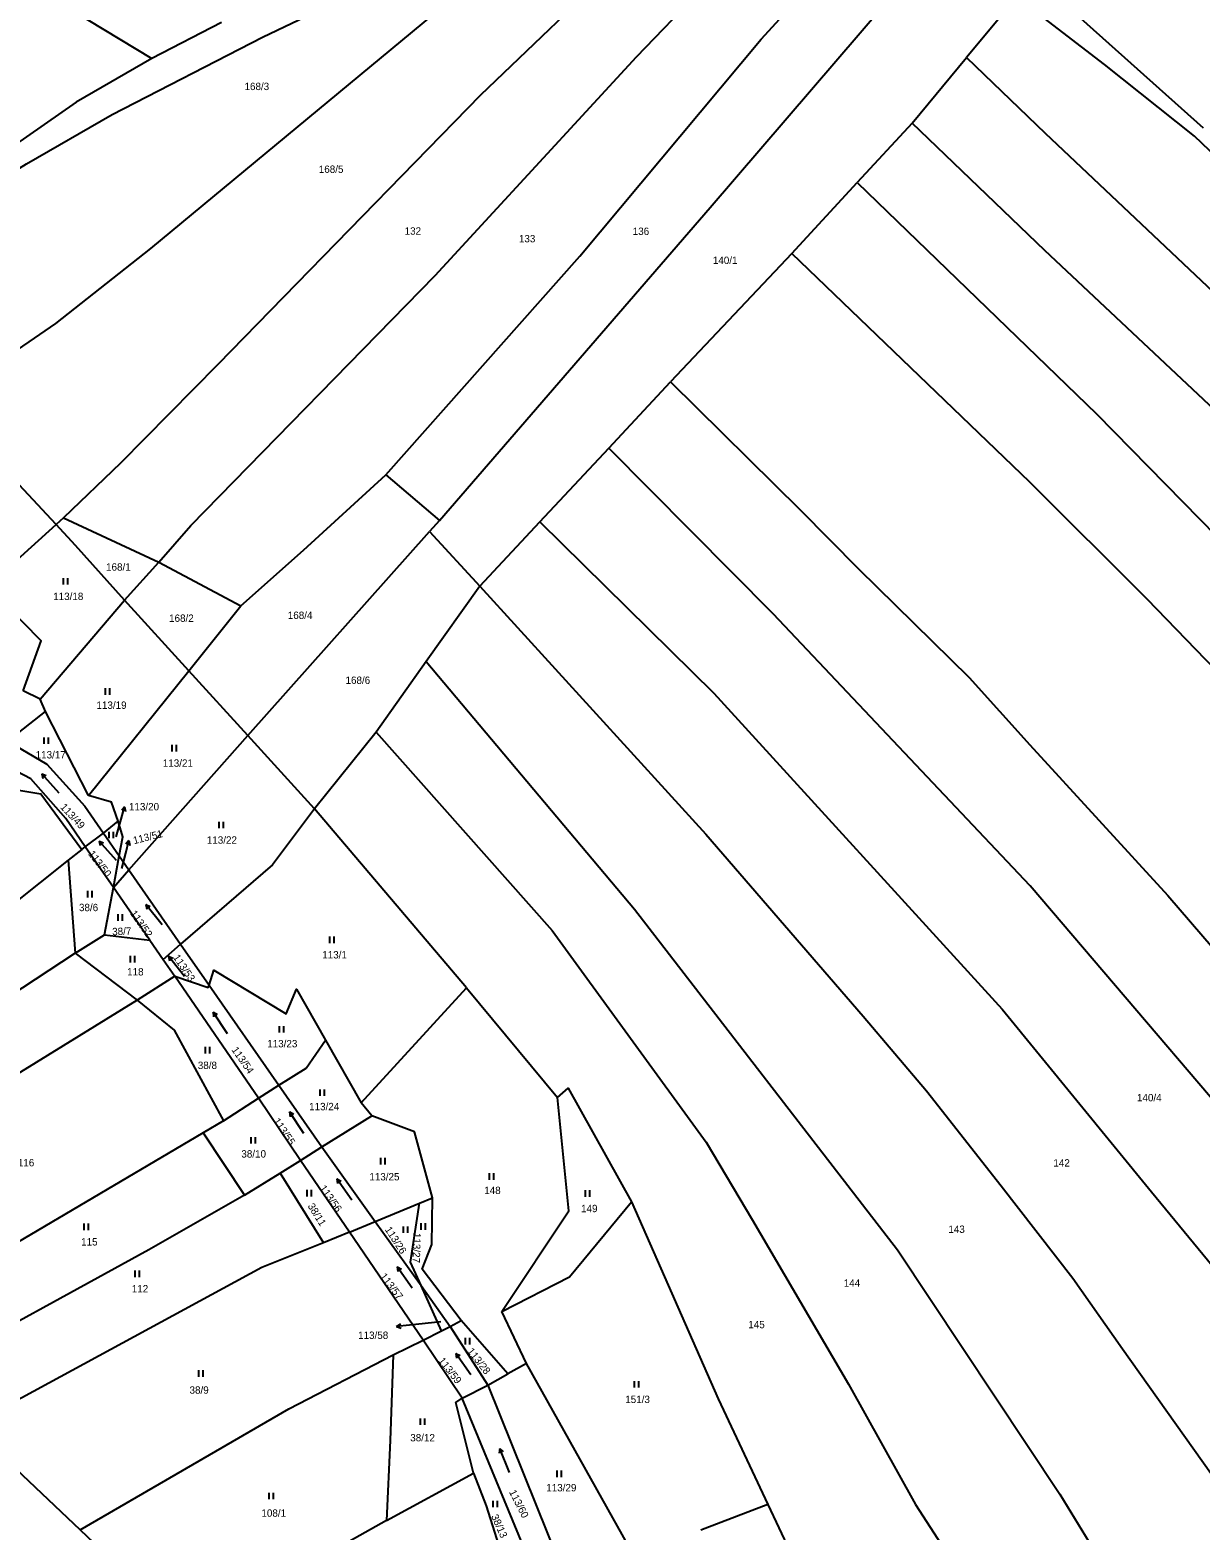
# Model space of a CAD drawing. Extents: x -751333 to -746055, y -1133395 to -1129777.
# Drawn here: x -747546.5 to -747276.5, y -1131141.4 to -1130795.4 of the extents above; entities that cross this region are included whole.
import ezdxf

# ---------------------------------------------------------------- set-up
doc = ezdxf.new("R2010")
doc.units = 0
for name, color, linetype in [('Hranice parcel', 7, 'Continuous'), ('Parcelní čísla', 7, 'Continuous'), ('Pop  PČ popisy', 7, 'Continuous'), ('Značky kultur', 7, 'Continuous')]:
    doc.layers.add(name, color=color, linetype=linetype)

msp = doc.modelspace()

# ---------------------------------------------------------------- linework, layer by layer
at = {"layer": 'Hranice parcel'}
for p, q in [((-747318.79, -1130787.77), (-747330.4, -1130801.79)), ((-747275.7, -1130818.09), (-747307.66, -1130789.55)), ((-747502.34, -1130793.69), (-747518.4, -1130801.96)), ((-747342.93, -1130816.92), (-747330.4, -1130801.79)), ((-747342.93, -1130816.92), (-747355.62, -1130830.63)), ((-747370.72, -1130846.96), (-747355.62, -1130830.63)), ((-747370.72, -1130846.96), (-747398.68, -1130876.61)), ((-747412.97, -1130891.88), (-747398.68, -1130876.61)), ((-747540.5, -1130909.52), (-747566.95, -1130881.22)), ((-747428.85, -1130908.85), (-747412.97, -1130891.88)), ((-747464.43, -1130898), (-747452.04, -1130908.53)), ((-747538.78, -1130907.97), (-747540.5, -1130909.52)), ((-747538.78, -1130907.97), (-747516.82, -1130918.2)), ((-747556.37, -1130923.79), (-747540.5, -1130909.52)), ((-747496.26, -1130958.17), (-747454.36, -1130911.13)), ((-747452.04, -1130908.53), (-747454.36, -1130911.13)), ((-747454.36, -1130911.13), (-747442.73, -1130923.69)), ((-747442.73, -1130923.69), (-747428.85, -1130908.85)), ((-747524.7, -1130926.96), (-747516.82, -1130918.2)), ((-747516.82, -1130918.2), (-747497.88, -1130928.23)), ((-747442.73, -1130923.69), (-747455.08, -1130941.09)), ((-747544.17, -1130949.82), (-747524.7, -1130926.96)), ((-747509.89, -1130943.21), (-747524.7, -1130926.96)), ((-747509.89, -1130943.21), (-747497.88, -1130928.23)), ((-747455.08, -1130941.09), (-747466.65, -1130957.41)), ((-747533.01, -1130972.03), (-747509.89, -1130943.21)), ((-747496.26, -1130958.17), (-747509.89, -1130943.21)), ((-747544.17, -1130949.82), (-747548.12, -1130947.84)), ((-747542.97, -1130952.61), (-747544.17, -1130949.82)), ((-747551.66, -1130959.44), (-747542.97, -1130952.61)), ((-747533.01, -1130972.03), (-747542.97, -1130952.61)), ((-747523.68, -1130989.16), (-747496.26, -1130958.17)), ((-747480.85, -1130975.08), (-747496.26, -1130958.17)), ((-747466.65, -1130957.41), (-747480.85, -1130975.08)), ((-747445.77, -1131016.39), (-747480.85, -1130975.08)), ((-747533.76, -1130983.87), (-747529.57, -1130980.67)), ((-747529.57, -1130980.67), (-747526.17, -1130977.92)), ((-747529.57, -1130980.67), (-747525.94, -1130985.9)), ((-747534.58, -1130984.5), (-747537.72, -1130986.92)), ((-747534.58, -1130984.5), (-747533.76, -1130983.87)), ((-747527.29, -1130993.25), (-747533.76, -1130983.87)), ((-747537.72, -1130986.92), (-747536.11, -1131008.38)), ((-747527.29, -1130993.25), (-747525.94, -1130985.9)), ((-747525.94, -1130985.9), (-747523.68, -1130989.16)), ((-747527.29, -1130993.25), (-747523.68, -1130989.16)), ((-747523.68, -1130989.16), (-747511.77, -1131006.31)), ((-747529.3, -1131004.16), (-747527.29, -1130993.25)), ((-747518.9, -1131005.41), (-747527.29, -1130993.25)), ((-747536.11, -1131008.38), (-747529.3, -1131004.16)), ((-747529.3, -1131004.16), (-747518.9, -1131005.41)), ((-747536.11, -1131008.38), (-747521.83, -1131019.25)), ((-747518.9, -1131005.41), (-747515.79, -1131009.83)), ((-747515.79, -1131009.83), (-747511.77, -1131006.31)), ((-747511.77, -1131006.31), (-747505.21, -1131015.73)), ((-747515.79, -1131009.83), (-747513.08, -1131013.69)), ((-747513.08, -1131013.69), (-747521.83, -1131019.25)), ((-747493.76, -1131041.86), (-747513.08, -1131013.69)), ((-747505.21, -1131015.73), (-747489.11, -1131038.86)), ((-747470.12, -1131042.87), (-747445.77, -1131016.39)), ((-747445.77, -1131016.39), (-747424.82, -1131041.7)), ((-747478.31, -1131028.41), (-747470.12, -1131042.87)), ((-747493.76, -1131041.86), (-747489.11, -1131038.86)), ((-747489.11, -1131038.86), (-747479.21, -1131053.09)), ((-747501.87, -1131047.09), (-747493.76, -1131041.86)), ((-747484.08, -1131056.18), (-747493.76, -1131041.86)), ((-747467.67, -1131045.88), (-747470.12, -1131042.87)), ((-747479.21, -1131053.09), (-747467.67, -1131045.88)), ((-747501.87, -1131047.09), (-747506.57, -1131049.83)), ((-747506.57, -1131049.83), (-747497.04, -1131064.23)), ((-747484.08, -1131056.18), (-747479.21, -1131053.09)), ((-747479.21, -1131053.09), (-747466.89, -1131070.28)), ((-747488.78, -1131059.1), (-747484.08, -1131056.18)), ((-747472.77, -1131072.73), (-747484.08, -1131056.18)), ((-747497.04, -1131064.23), (-747488.78, -1131059.1)), ((-747488.78, -1131059.1), (-747478.83, -1131075.18)), ((-747466.89, -1131070.28), (-747456.65, -1131066.03)), ((-747456.65, -1131066.03), (-747453.62, -1131064.84)), ((-747472.77, -1131072.73), (-747466.89, -1131070.28)), ((-747466.89, -1131070.28), (-747456.29, -1131085.07)), ((-747472.77, -1131072.73), (-747478.83, -1131075.18)), ((-747455.83, -1131097.63), (-747472.77, -1131072.73)), ((-747456.29, -1131085.07), (-747449.55, -1131094.47)), ((-747451.56, -1131095.48), (-747456.29, -1131085.07)), ((-747431.95, -1131103.02), (-747437.65, -1131091.07)), ((-747451.56, -1131095.48), (-747449.55, -1131094.47)), ((-747449.55, -1131094.47), (-747447.06, -1131093.1)), ((-747449.55, -1131094.47), (-747440.84, -1131108.03)), ((-747436.27, -1131105.41), (-747447.06, -1131093.1)), ((-747462.74, -1131101.03), (-747455.83, -1131097.63)), ((-747455.83, -1131097.63), (-747451.56, -1131095.48)), ((-747446.81, -1131111.05), (-747455.83, -1131097.63)), ((-747440.84, -1131108.03), (-747436.27, -1131105.41)), ((-747431.95, -1131103.02), (-747436.27, -1131105.41)), ((-747408.38, -1131145.07), (-747431.95, -1131103.02)), ((-747446.81, -1131111.05), (-747440.84, -1131108.03)), ((-747440.84, -1131108.03), (-747424.22, -1131149.41)), ((-747430.18, -1131151.04), (-747446.81, -1131111.05)), ((-747551.23, -1131125.94), (-747534.94, -1131141.41)), ((-747464.26, -1131139.24), (-747444.14, -1131128.36)), ((-747376.22, -1131135.6), (-747391.74, -1131141.48)), ((-747518.15, -1131157.34), (-747534.94, -1131141.41))]:
    msp.add_line(p, q, dxfattribs=at)
for points in [[(-747650.43, -1130722.5), (-747624.13, -1130740.43), (-747611.24, -1130748.86), (-747568.75, -1130772.25), (-747551.99, -1130781.63), (-747518.4, -1130801.96)], [(-747592.89, -1130855.02), (-747567.07, -1130838.41), (-747547.35, -1130826.32), (-747527.53, -1130814.88), (-747492.89, -1130797.06), (-747472.69, -1130787.42), (-747441.69, -1130763.28), (-747417.46, -1130747.1), (-747393.87, -1130731.74)], [(-747566.95, -1130881.22), (-747540.53, -1130863.15), (-747518.65, -1130845.8), (-747451.1, -1130789.94), (-747421.34, -1130761.04), (-747390.31, -1130735.18)], [(-747375.64, -1130746.37), (-747442.58, -1130810.47), (-747503.21, -1130872.55), (-747525.65, -1130895.32), (-747538.78, -1130907.97)], [(-747516.82, -1130918.2), (-747509.43, -1130909.76), (-747453.02, -1130852.06), (-747406.54, -1130801.59), (-747362.47, -1130755.89)], [(-747464.43, -1130898), (-747419.65, -1130847.56), (-747377.79, -1130797.57), (-747349.46, -1130766.63)], [(-747452.04, -1130908.53), (-747389.53, -1130836.33), (-747337.16, -1130775.31)], [(-747003.4, -1131127.9), (-747038.28, -1131074.83), (-747088.46, -1131014.6), (-747116.47, -1130986.19), (-747124.97, -1130976.78), (-747183.56, -1130913.69), (-747214.38, -1130881.51), (-747246.16, -1130850.11), (-747277.78, -1130819.92), (-747298.57, -1130803.35), (-747318.79, -1130787.77)], [(-747518.4, -1130801.96), (-747535.86, -1130812.1), (-747550.62, -1130822.39), (-747567.45, -1130834.27)], [(-747330.4, -1130801.79), (-747312.28, -1130819.2), (-747236.13, -1130891.14), (-747221.8, -1130905.72), (-747180.22, -1130949.79), (-747146.85, -1130983.32), (-747109.33, -1131021.53), (-747071.58, -1131064.23), (-747049.91, -1131090.84), (-747024.34, -1131132)], [(-747047.94, -1131136.47), (-747061.48, -1131111.93), (-747077.88, -1131090.42), (-747092.86, -1131072.81), (-747117.23, -1131044.76), (-747147.18, -1131012.65), (-747177.53, -1130980.93), (-747224.92, -1130930.97), (-747274.38, -1130881.89), (-747312.29, -1130846.28), (-747342.93, -1130816.92)], [(-747355.62, -1130830.63), (-747300.42, -1130884), (-747284.49, -1130900.18), (-747229.45, -1130956.25), (-747195.44, -1130993.87), (-747158.72, -1131032.34), (-747137.46, -1131054.25), (-747087.92, -1131108.9), (-747067.99, -1131140.68)], [(-747092.53, -1131145.47), (-747103.44, -1131128.5), (-747151.55, -1131074.46), (-747210.89, -1131009.26), (-747228.17, -1130990.46), (-747257.09, -1130959.39), (-747288.71, -1130926.72), (-747315.79, -1130899.71), (-747370.72, -1130846.96)], [(-747398.68, -1130876.61), (-747368.77, -1130906.07), (-747355.31, -1130919.74), (-747329.82, -1130944.76), (-747315.8, -1130960.3), (-747283.94, -1130995.04), (-747236.86, -1131049.77), (-747149.88, -1131157.26)], [(-747177.21, -1131162.4), (-747204.46, -1131125.99), (-747254.48, -1131065.07), (-747271.84, -1131044.18), (-747315.73, -1130992.85), (-747375, -1130930.12), (-747412.97, -1130891.88)], [(-747497.88, -1130928.23), (-747483.39, -1130915.42), (-747464.43, -1130898)], [(-747524.7, -1130926.96), (-747536.03, -1130914.31), (-747540.5, -1130909.52)], [(-747428.85, -1130908.85), (-747388.68, -1130948.41), (-747322.17, -1131021.26), (-747287.68, -1131063.4), (-747257.57, -1131100.06), (-747233.11, -1131129.78), (-747216.94, -1131150.33), (-747204.99, -1131167.77)], [(-747548.12, -1130947.84), (-747543.96, -1130936.32), (-747556.37, -1130923.79)], [(-747442.73, -1130923.69), (-747390.58, -1130980.92), (-747354.26, -1131022.92), (-747339.61, -1131040.16), (-747322.4, -1131062.04), (-747305.83, -1131083.32), (-747294.44, -1131099.65), (-747274.04, -1131128.34), (-747243.06, -1131175.98)], [(-747455.08, -1130941.09), (-747407, -1130998.24), (-747346.3, -1131076.82), (-747308.86, -1131133.19), (-747276.68, -1131185.78)], [(-747551.66, -1130959.44), (-747542.61, -1130964.81), (-747533.86, -1130974.48), (-747529.57, -1130980.67)], [(-747466.65, -1130957.41), (-747426.05, -1131003.14), (-747390.52, -1131051.98), (-747379.77, -1131069.99), (-747357.62, -1131107.84), (-747342.16, -1131135.57), (-747326.23, -1131160.19), (-747318.42, -1131169.83), (-747304.55, -1131193.5)], [(-747533.76, -1130983.87), (-747538.28, -1130977.32), (-747546.35, -1130968.19), (-747556.12, -1130963.07)], [(-747562.63, -1130968.51), (-747544.05, -1130971.62), (-747534.58, -1130984.5)], [(-747526.17, -1130977.92), (-747527.69, -1130973.54), (-747533.01, -1130972.03)], [(-747480.85, -1130975.08), (-747490.53, -1130988), (-747511.77, -1131006.31)], [(-747525.94, -1130985.9), (-747525.13, -1130981.52), (-747526.17, -1130977.92)], [(-747537.72, -1130986.92), (-747564.39, -1131008.14), (-747611.03, -1131036.67), (-747627.11, -1131046.39)], [(-747536.11, -1131008.38), (-747587.97, -1131042.46), (-747616.38, -1131059.15)], [(-747513.08, -1131013.69), (-747505.41, -1131016.33), (-747505.21, -1131015.73)], [(-747505.21, -1131015.73), (-747504.08, -1131012.3), (-747487.41, -1131022.36), (-747485.06, -1131016.72), (-747478.31, -1131028.41)], [(-747521.83, -1131019.25), (-747565.86, -1131046.34), (-747605.42, -1131071.52)], [(-747521.83, -1131019.25), (-747513.23, -1131026.12), (-747501.87, -1131047.09)], [(-747489.11, -1131038.86), (-747482.82, -1131034.88), (-747478.31, -1131028.41)], [(-747424.82, -1131041.7), (-747422.32, -1131039.54), (-747407.71, -1131065.71)], [(-747437.65, -1131091.07), (-747422.19, -1131067.82), (-747424.82, -1131041.7)], [(-747453.62, -1131064.84), (-747457.76, -1131049.58), (-747467.67, -1131045.88)], [(-747506.57, -1131049.83), (-747567.11, -1131085.51), (-747578.6, -1131091.89), (-747583.1, -1131094.79)], [(-747497.04, -1131064.23), (-747519.1, -1131076.81), (-747571.91, -1131105.73)], [(-747456.29, -1131085.07), (-747458.74, -1131079.69), (-747456.65, -1131066.03)], [(-747447.06, -1131093.1), (-747456, -1131081.28), (-747453.76, -1131075.58), (-747453.62, -1131064.84)], [(-747437.65, -1131091.07), (-747422, -1131083.03), (-747407.71, -1131065.71)], [(-747407.71, -1131065.71), (-747387.68, -1131111.18), (-747376.22, -1131135.6)], [(-747478.83, -1131075.18), (-747493.05, -1131080.92), (-747560.11, -1131117.26)], [(-747534.94, -1131141.41), (-747486.76, -1131113.5), (-747462.74, -1131101.03)], [(-747462.74, -1131101.03), (-747463.44, -1131120.77), (-747464.26, -1131139.24)], [(-747444.14, -1131128.36), (-747448.25, -1131112.03), (-747446.81, -1131111.05)], [(-747444.14, -1131128.36), (-747441.29, -1131135.89), (-747437.88, -1131146.58), (-747434.26, -1131152.16)], [(-747376.22, -1131135.6), (-747368.67, -1131151.69), (-747335.3, -1131202.07)], [(-747464.26, -1131139.24), (-747483.41, -1131150.03), (-747508, -1131163.09)]]:
    msp.add_lwpolyline(points, dxfattribs=at)
at = {"layer": 'Pop  PČ popisy'}
for p, q in [((-747526.65, -1130981.51), (-747525.51, -1130977.47)), ((-747525.51, -1130977.47), (-747524.683, -1130974.585)), ((-747524.683, -1130974.585), (-747525.44, -1130975.41)), ((-747524.683, -1130974.585), (-747524.478, -1130975.686)), ((-747523.704, -1130982.418), (-747524.432, -1130983.269)), ((-747524.43, -1130985.33), (-747523.704, -1130982.418)), ((-747523.704, -1130982.418), (-747523.46, -1130983.511)), ((-747525.3, -1130988.86), (-747524.43, -1130985.33)), ((-747461.915, -1131094.514), (-747460.971, -1131093.911)), ((-747458.93, -1131094.2), (-747461.915, -1131094.514)), ((-747461.915, -1131094.514), (-747460.866, -1131094.907)), ((-747451.68, -1131093.42), (-747458.93, -1131094.2))]:
    msp.add_line(p, q, dxfattribs=at)
at = {"layer": 'Značky kultur'}
for p, q in [((-747538.761, -1130923.37), (-747538.761, -1130921.87)), ((-747537.76, -1130923.37), (-747537.76, -1130921.87)), ((-747529.101, -1130948.78), (-747529.101, -1130947.28)), ((-747528.1, -1130948.78), (-747528.1, -1130947.28)), ((-747543.241, -1130960.1), (-747543.241, -1130958.6)), ((-747542.24, -1130960.1), (-747542.24, -1130958.6)), ((-747513.741, -1130961.83), (-747513.741, -1130960.33)), ((-747512.74, -1130961.83), (-747512.74, -1130960.33)), ((-747539.798, -1130971.471), (-747543.812, -1130967.012)), ((-747543.812, -1130967.012), (-747543.531, -1130968.074)), ((-747543.812, -1130967.012), (-747542.786, -1130967.403)), ((-747528.221, -1130981.85), (-747528.221, -1130980.35)), ((-747527.22, -1130981.85), (-747527.22, -1130980.35)), ((-747502.901, -1130979.58), (-747502.901, -1130978.08)), ((-747501.9, -1130979.58), (-747501.9, -1130978.08)), ((-747526.568, -1130986.971), (-747530.582, -1130982.512)), ((-747530.582, -1130982.512), (-747530.301, -1130983.574)), ((-747530.582, -1130982.512), (-747529.556, -1130982.903)), ((-747533.171, -1130995.51), (-747533.171, -1130994.01)), ((-747532.17, -1130995.51), (-747532.17, -1130994.01)), ((-747515.996, -1131001.813), (-747519.772, -1130997.15)), ((-747519.772, -1130997.15), (-747519.547, -1130998.225)), ((-747519.772, -1130997.15), (-747518.767, -1130997.594)), ((-747526.201, -1131000.89), (-747526.201, -1130999.39)), ((-747525.2, -1131000.89), (-747525.2, -1130999.39)), ((-747477.301, -1131006.05), (-747477.301, -1131004.55)), ((-747476.3, -1131006.05), (-747476.3, -1131004.55)), ((-747523.331, -1131010.52), (-747523.331, -1131009.02)), ((-747522.33, -1131010.52), (-747522.33, -1131009.02)), ((-747510.867, -1131013.795), (-747514.561, -1131009.067)), ((-747514.561, -1131009.067), (-747514.354, -1131010.146)), ((-747514.561, -1131009.067), (-747513.564, -1131009.528)), ((-747500.925, -1131026.978), (-747504.28, -1131022.004)), ((-747504.28, -1131022.004), (-747504.149, -1131023.094)), ((-747504.28, -1131022.004), (-747503.318, -1131022.534)), ((-747488.941, -1131026.68), (-747488.941, -1131025.18)), ((-747487.94, -1131026.68), (-747487.94, -1131025.18)), ((-747506.041, -1131031.49), (-747506.041, -1131029.99)), ((-747505.04, -1131031.49), (-747505.04, -1131029.99)), ((-747479.541, -1131041.31), (-747479.541, -1131039.81)), ((-747478.54, -1131041.31), (-747478.54, -1131039.81)), ((-747483.295, -1131049.988), (-747486.65, -1131045.014)), ((-747486.65, -1131045.014), (-747486.519, -1131046.104)), ((-747486.65, -1131045.014), (-747485.688, -1131045.544)), ((-747495.491, -1131052.29), (-747495.491, -1131050.79)), ((-747494.49, -1131052.29), (-747494.49, -1131050.79)), ((-747465.541, -1131057.13), (-747465.541, -1131055.63)), ((-747464.54, -1131057.13), (-747464.54, -1131055.63)), ((-747472.252, -1131065.368), (-747475.694, -1131060.454)), ((-747475.694, -1131060.454), (-747475.544, -1131061.542)), ((-747475.694, -1131060.454), (-747474.722, -1131060.966)), ((-747440.461, -1131060.63), (-747440.461, -1131059.13)), ((-747439.46, -1131060.63), (-747439.46, -1131059.13)), ((-747482.541, -1131064.49), (-747482.541, -1131062.99)), ((-747481.54, -1131064.49), (-747481.54, -1131062.99)), ((-747418.341, -1131064.58), (-747418.341, -1131063.08)), ((-747417.34, -1131064.58), (-747417.34, -1131063.08)), ((-747533.991, -1131072.27), (-747533.991, -1131070.77)), ((-747532.99, -1131072.27), (-747532.99, -1131070.77)), ((-747456.231, -1131072.2), (-747456.231, -1131070.7)), ((-747455.23, -1131072.2), (-747455.23, -1131070.7)), ((-747460.341, -1131072.91), (-747460.341, -1131071.41)), ((-747459.34, -1131072.91), (-747459.34, -1131071.41)), ((-747458.352, -1131085.648), (-747461.794, -1131080.734)), ((-747461.794, -1131080.734), (-747461.644, -1131081.822)), ((-747461.794, -1131080.734), (-747460.822, -1131081.246)), ((-747522.271, -1131083.09), (-747522.271, -1131081.59)), ((-747521.27, -1131083.09), (-747521.27, -1131081.59)), ((-747446.041, -1131098.65), (-747446.041, -1131097.15)), ((-747445.04, -1131098.65), (-747445.04, -1131097.15)), ((-747444.812, -1131105.628), (-747448.254, -1131100.714)), ((-747448.254, -1131100.714), (-747448.104, -1131101.802)), ((-747448.254, -1131100.714), (-747447.282, -1131101.226)), ((-747507.601, -1131106.09), (-747507.601, -1131104.59)), ((-747506.6, -1131106.09), (-747506.6, -1131104.59)), ((-747407.041, -1131108.61), (-747407.041, -1131107.11)), ((-747406.04, -1131108.61), (-747406.04, -1131107.11)), ((-747456.411, -1131117.21), (-747456.411, -1131115.71)), ((-747455.41, -1131117.21), (-747455.41, -1131115.71)), ((-747438.132, -1131122.639), (-747438.231, -1131123.733)), ((-747435.885, -1131128.202), (-747438.132, -1131122.639)), ((-747438.132, -1131122.639), (-747437.301, -1131123.358)), ((-747424.881, -1131129.23), (-747424.881, -1131127.73)), ((-747423.88, -1131129.23), (-747423.88, -1131127.73)), ((-747491.321, -1131134.35), (-747491.321, -1131132.85)), ((-747490.32, -1131134.35), (-747490.32, -1131132.85)), ((-747439.631, -1131136.2), (-747439.631, -1131134.7)), ((-747438.63, -1131136.2), (-747438.63, -1131134.7))]:
    msp.add_line(p, q, dxfattribs=at)

# ---------------------------------------------------------------- texts
at = {"layer": 'Parcelní čísla'}
for s, p in [('168/3', (-747497.02, -1130809.28)), ('168/5', (-747479.88, -1130828.38)), ('132', (-747460.07, -1130842.63)), ('136', (-747407.43, -1130842.7)), ('133', (-747433.7, -1130844.4)), ('140/1', (-747388.94, -1130849.39)), ('168/1', (-747528.97, -1130920.14)), ('113/18', (-747541.17, -1130926.92)), ('168/2', (-747514.43, -1130931.95)), ('168/4', (-747487.03, -1130931.28)), ('168/6', (-747473.71, -1130946.27)), ('113/19', (-747531.19, -1130952.02)), ('113/17', (-747545.22, -1130963.46)), ('113/21', (-747515.88, -1130965.38)), ('113/20', (-747523.69, -1130975.43)), ('113/22', (-747505.72, -1130983.13)), ('38/6', (-747535.22, -1130998.69)), ('113/1', (-747479.08, -1131009.6)), ('118', (-747524.11, -1131013.52)), ('113/23', (-747491.78, -1131030.1)), ('38/8', (-747507.8, -1131035.1)), ('113/24', (-747482.11, -1131044.61)), ('140/4', (-747291.06, -1131042.55)), ('116', (-747549.33, -1131057.56)), ('38/10', (-747497.75, -1131055.53)), ('142', (-747310.35, -1131057.61)), ('113/25', (-747468.21, -1131060.8)), ('148', (-747441.7, -1131063.95)), ('149', (-747419.35, -1131068.13)), ('115', (-747534.73, -1131075.82)), ('143', (-747334.59, -1131072.91)), ('144', (-747358.73, -1131085.33)), ('112', (-747523.04, -1131086.64)), ('145', (-747380.76, -1131094.9)), ('113/58', (-747470.805, -1131097.368)), ('38/9', (-747509.71, -1131110.01)), ('151/3', (-747409.16, -1131112.16)), ('38/12', (-747458.77, -1131121)), ('113/29', (-747427.38, -1131132.53)), ('108/1', (-747493.12, -1131138.39))]:
    msp.add_text(s, height=1.7, dxfattribs=at).set_placement(p)
for s, rotation, p in [('113/49', 313, (-747539.661, -1130974.799)), ('113/51', 14, (-747522.504, -1130983.244)), ('113/50', 308, (-747533.209, -1130985.523)), ('113/52', 305, (-747523.516, -1130999.227)), ('38/7', 2, (-747527.53, -1131004.259)), ('113/53', 304, (-747513.584, -1131009.355)), ('113/54', 305, (-747500.096, -1131030.697)), ('113/55', 304, (-747490.464, -1131047.105)), ('113/56', 305, (-747479.786, -1131062.597)), ('38/11', 302, (-747482.52, -1131066.7)), ('113/26', 303, (-747464.712, -1131072.122)), ('113/27', 268, (-747458.019, -1131072.87)), ('113/57', 307, (-747465.838, -1131082.951)), ('113/59', 308, (-747452.399, -1131102.423)), ('113/28', 308, (-747445.719, -1131100.243)), ('113/60', 297, (-747436.017, -1131132.675)), ('38/13', 294, (-747440.146, -1131138.275))]:
    msp.add_text(s, height=1.7, rotation=rotation, dxfattribs=at).set_placement(p)

doc.saveas('drawing.dxf')
